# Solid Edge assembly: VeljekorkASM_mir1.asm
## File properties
Author: KULL
Template: Iso Metric Assembly.asm
Last saved by: KULL
Revision: 2
Application: Solid Edge
Username: KULL
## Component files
rehvikork_mir1.par
rehvikork_logo_mir1.par
VeljekorkASM.asm
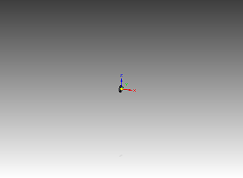
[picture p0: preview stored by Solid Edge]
